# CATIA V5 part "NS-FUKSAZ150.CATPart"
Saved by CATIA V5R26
Part number: NS-FUKSAZ150
Bounding box of the stored display mesh (mm): x -99.1 to 99.1, y 0 to 198, z -49.9 to 49.9
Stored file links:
  R:\Document\坂尻\その他\ナベヤデータ変換\安全カバーキャスター\MCBKSAZ150\NS-FUKSAZ150.CATPart
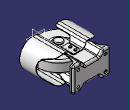
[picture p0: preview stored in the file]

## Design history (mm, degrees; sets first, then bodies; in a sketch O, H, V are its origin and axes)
Body1 (main body)
  Solid1: solid without history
